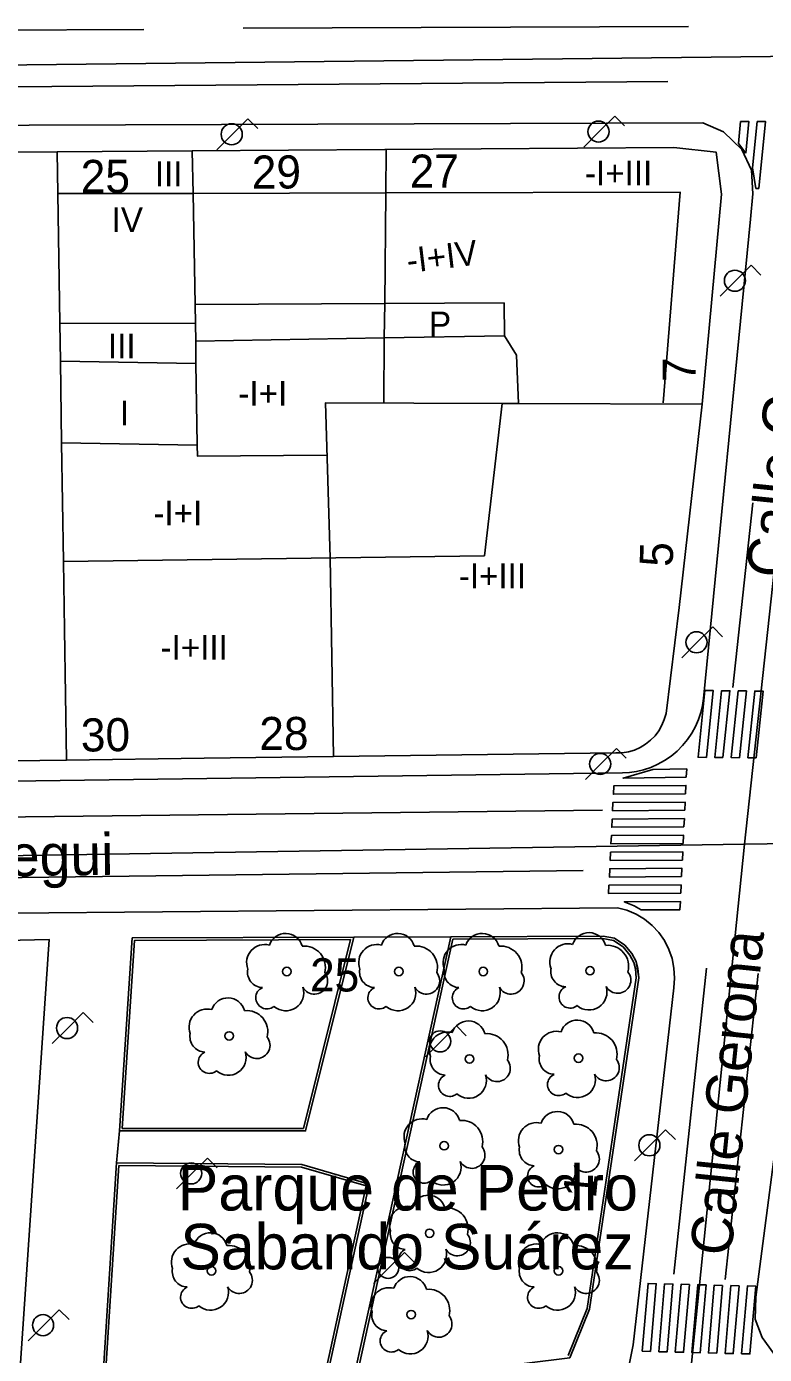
# Model space of a CAD drawing. Extents: x 282771 to 285132, y 4823109 to 4825496.
# Drawn here: x 283003.1 to 283047.7, y 4824352.9 to 4824433.2 of the extents above; entities that cross this region are included whole.
import ezdxf

# ---------------------------------------------------------------- set-up
doc = ezdxf.new("R2010")
doc.units = 0
for name, color, linetype in [('ACERA-BORDILLO', 7, 'Continuous'), ('ACERA-INTERIOR', 7, 'Continuous'), ('ARBOL', 7, 'Continuous'), ('BORDILLO', 7, 'Continuous'), ('CALLE-EJE', 7, 'Continuous'), ('CALLE-TEXTO', 7, 'Continuous'), ('EDIFICIO', 7, 'Continuous'), ('FAROLA', 7, 'Continuous'), ('INTERIOR-EDIFICIO', 7, 'Continuous'), ('MEDIANERA', 7, 'Continuous'), ('NUM-LOCAL', 7, 'Continuous'), ('NUM-PORTAL', 7, 'Continuous'), ('NUM-VADO', 7, 'Continuous'), ('PARQUE-JARDIN-AREA', 7, 'Continuous'), ('PARQUE-JARDIN-TEXTO', 7, 'Continuous'), ('PASO-PEATONES', 7, 'Continuous'), ('SENAL-VIARIA', 7, 'Continuous'), ('TXT-ALTURA-EDIFICIO', 7, 'Continuous'), ('ZONA-VERDE', 7, 'Continuous')]:
    doc.layers.add(name, color=color, linetype=linetype)

msp = doc.modelspace()

# ---------------------------------------------------------------- linework, layer by layer
at = {"layer": 'ACERA-BORDILLO'}
for points in [[(282941.637, 4824386.754), (283039.135, 4824388.075), (283039.556, 4824388.099), (283039.985, 4824388.161), (283040.418, 4824388.262), (283040.85, 4824388.405), (283041.274, 4824388.59), (283041.684, 4824388.816), (283042.074, 4824389.083), (283042.44, 4824389.387), (283042.774, 4824389.724), (283043.074, 4824390.089), (283043.336, 4824390.478), (283043.558, 4824390.884), (283043.738, 4824391.301), (283043.877, 4824391.723), (283043.976, 4824392.146), (283044.037, 4824392.563), (283046.872, 4824421.522), (283047.025, 4824423.063), (283046.94, 4824424.485), (283046.348, 4824425.738), (283045.247, 4824426.805), (283043.995, 4824427.347), (282956.749, 4824427.04)], [(283038.839, 4824379.93), (282983.849, 4824379.43), (282942.342, 4824378.862), (282941.159, 4824378.712), (282940.133, 4824378.39), (282939.066, 4824377.686), (282938.302, 4824376.679), (282938, 4824375.834), (282937.92, 4824374.727), (282938.04, 4824373.801), (282943.253, 4824342.596)], [(283039.561, 4824352.416), (283039.782, 4824353.523), (283042.239, 4824375.09), (283042.289, 4824375.68), (283042.249, 4824376.27), (283042.139, 4824376.85), (283041.949, 4824377.41), (283041.679, 4824377.94), (283041.329, 4824378.43), (283040.929, 4824378.86), (283040.469, 4824379.24), (283039.959, 4824379.54), (283039.409, 4824379.77), (283038.839, 4824379.93)], [(283048.263, 4824353.014), (283047.579, 4824353.961), (283047.157, 4824355.068), (283047.197, 4824356.396), (283049.765, 4824376.004)]]:
    msp.add_lwpolyline(points, dxfattribs=at)
at = {"layer": 'ACERA-INTERIOR'}
msp.add_lwpolyline([(283002.516, 4824348.556), (283004.514, 4824378.006), (283000.089, 4824377.912)], dxfattribs=at)
at = {"layer": 'ARBOL'}
for centre in [(283018.861, 4824376.077), (283025.632, 4824376.077), (283030.733, 4824376.077), (283037.18, 4824376.124), (283015.382, 4824372.182), (283029.898, 4824370.79), (283036.484, 4824370.837), (283028.368, 4824365.55), (283035.278, 4824365.318), (283027.487, 4824360.263), (283014.316, 4824357.99), (283035.278, 4824357.99), (283026.374, 4824355.347)]:
    msp.add_circle(centre, 0.255, dxfattribs=at)
for centre, radius, start, end in [((283018.791, 4824377.337), 1.038, 15.64228, 161.38435), ((283025.562, 4824377.337), 1.038, 15.64228, 161.38435), ((283030.663, 4824377.337), 1.038, 15.64228, 161.38435), ((283037.11, 4824377.384), 1.038, 15.64228, 161.38435), ((283017.531, 4824376.607), 1.097, 75.4318, 200.55608), ((283019.921, 4824376.337), 1.272, 345.03273, 95.79925), ((283024.302, 4824376.607), 1.097, 75.4318, 200.55608), ((283026.692, 4824376.337), 1.272, 345.03273, 95.79925), ((283029.403, 4824376.607), 1.097, 75.4318, 200.55608), ((283031.793, 4824376.337), 1.272, 345.03273, 95.79925), ((283035.85, 4824376.654), 1.097, 75.4318, 200.55608), ((283038.24, 4824376.384), 1.272, 345.03273, 95.79925), ((283035.74, 4824376.084), 0.935, 168.59898, 268.13236), ((283017.421, 4824376.037), 0.935, 168.59898, 268.13236), ((283020.531, 4824375.507), 0.797, 208.96247, 38.99103), ((283024.192, 4824376.037), 0.935, 168.59898, 268.13236), ((283027.302, 4824375.507), 0.797, 208.96247, 38.99103), ((283029.293, 4824376.037), 0.935, 168.59898, 268.13236), ((283032.403, 4824375.507), 0.797, 208.96247, 38.99103), ((283038.85, 4824375.554), 0.797, 208.96247, 38.99103), ((283017.661, 4824374.487), 0.672, 113.73672, 309.4725), ((283018.801, 4824374.787), 1.086, 228.95447, 17.92796), ((283024.432, 4824374.487), 0.672, 113.73672, 309.4725), ((283025.572, 4824374.787), 1.086, 228.95447, 17.92796), ((283029.533, 4824374.487), 0.672, 113.73672, 309.4725), ((283030.673, 4824374.787), 1.086, 228.95447, 17.92796), ((283035.98, 4824374.534), 0.672, 113.73672, 309.4725), ((283037.12, 4824374.834), 1.086, 228.95447, 17.92796), ((283015.312, 4824373.442), 1.038, 15.64228, 161.38435), ((283014.052, 4824372.712), 1.097, 75.4318, 200.55608), ((283016.442, 4824372.442), 1.272, 345.03273, 95.79925), ((283029.828, 4824372.05), 1.038, 15.64228, 161.38435), ((283036.414, 4824372.097), 1.038, 15.64228, 161.38435), ((283013.942, 4824372.142), 0.935, 168.59898, 268.13236), ((283028.569, 4824371.32), 1.097, 75.4318, 200.55608), ((283030.958, 4824371.05), 1.272, 345.03273, 95.79925), ((283035.154, 4824371.367), 1.097, 75.4318, 200.55608), ((283037.544, 4824371.097), 1.272, 345.03273, 95.79925), ((283017.052, 4824371.612), 0.797, 208.96247, 38.99103), ((283014.182, 4824370.592), 0.672, 113.73672, 309.4725), ((283015.322, 4824370.892), 1.086, 228.95447, 17.92796), ((283028.459, 4824370.75), 0.935, 168.59898, 268.13236), ((283031.568, 4824370.22), 0.797, 208.96247, 38.99103), ((283035.044, 4824370.797), 0.935, 168.59898, 268.13236), ((283038.154, 4824370.267), 0.797, 208.96247, 38.99103), ((283028.699, 4824369.2), 0.672, 113.73672, 309.4725), ((283029.838, 4824369.5), 1.086, 228.95447, 17.92796), ((283035.284, 4824369.247), 0.672, 113.73672, 309.4725), ((283036.424, 4824369.547), 1.086, 228.95447, 17.92796), ((283028.298, 4824366.81), 1.038, 15.64228, 161.38435), ((283035.208, 4824366.578), 1.038, 15.64228, 161.38435), ((283027.038, 4824366.08), 1.097, 75.4318, 200.55608), ((283029.428, 4824365.81), 1.272, 345.03273, 95.79925), ((283033.948, 4824365.848), 1.097, 75.4318, 200.55608), ((283036.338, 4824365.578), 1.272, 345.03273, 95.79925), ((283026.928, 4824365.51), 0.935, 168.59898, 268.13236), ((283030.038, 4824364.98), 0.797, 208.96247, 38.99103), ((283033.838, 4824365.278), 0.935, 168.59898, 268.13236), ((283036.948, 4824364.748), 0.797, 208.96247, 38.99103), ((283027.168, 4824363.96), 0.672, 113.73672, 309.4725), ((283028.308, 4824364.26), 1.086, 228.95447, 17.92796), ((283034.078, 4824363.728), 0.672, 113.73672, 309.4725), ((283035.218, 4824364.028), 1.086, 228.95447, 17.92796), ((283026.157, 4824360.793), 1.097, 75.4318, 200.55608), ((283027.417, 4824361.523), 1.038, 15.64228, 161.38435), ((283028.547, 4824360.523), 1.272, 345.03273, 95.79925), ((283014.246, 4824359.25), 1.038, 15.64228, 161.38435), ((283026.047, 4824360.223), 0.935, 168.59898, 268.13236), ((283029.157, 4824359.693), 0.797, 208.96247, 38.99103), ((283035.208, 4824359.25), 1.038, 15.64228, 161.38435), ((283012.986, 4824358.52), 1.097, 75.4318, 200.55608), ((283015.376, 4824358.25), 1.272, 345.03273, 95.79925), ((283033.948, 4824358.52), 1.097, 75.4318, 200.55608), ((283036.338, 4824358.25), 1.272, 345.03273, 95.79925), ((283026.287, 4824358.673), 0.672, 113.73672, 309.4725), ((283027.427, 4824358.973), 1.086, 228.95447, 17.92796), ((283012.876, 4824357.95), 0.935, 168.59898, 268.13236), ((283015.986, 4824357.42), 0.797, 208.96247, 38.99103), ((283033.838, 4824357.95), 0.935, 168.59898, 268.13236), ((283036.948, 4824357.42), 0.797, 208.96247, 38.99103), ((283013.116, 4824356.4), 0.672, 113.73672, 309.4725), ((283014.256, 4824356.7), 1.086, 228.95447, 17.92796), ((283025.044, 4824355.877), 1.097, 75.4318, 200.55608), ((283026.304, 4824356.607), 1.038, 15.64228, 161.38435), ((283034.078, 4824356.4), 0.672, 113.73672, 309.4725), ((283035.218, 4824356.7), 1.086, 228.95447, 17.92796), ((283027.434, 4824355.607), 1.272, 345.03273, 95.79925), ((283024.934, 4824355.307), 0.935, 168.59898, 268.13236), ((283028.044, 4824354.777), 0.797, 208.96247, 38.99103), ((283025.174, 4824353.757), 0.672, 113.73672, 309.4725), ((283026.314, 4824354.057), 1.086, 228.95447, 17.92796)]:
    msp.add_arc(centre, radius, start, end, dxfattribs=at)
at = {"layer": 'BORDILLO'}
for points in [[(283008.749, 4824366.44), (283009.527, 4824378.105), (283022.903, 4824378.156), (283019.994, 4824366.44), (283008.749, 4824366.44)], [(283022.818, 4824351.096), (283028.778, 4824378.178), (283037.968, 4824378.213), (283038.663, 4824378.085), (283039.279, 4824377.671), (283039.702, 4824377.152), (283039.971, 4824376.671), (283040.067, 4824376.258), (283040.129, 4824375.69), (283037.145, 4824355.673), (283035.959, 4824352.74), (283022.818, 4824351.096)], [(283008.579, 4824364.506), (283019.768, 4824364.413), (283023.835, 4824363.231), (283021.146, 4824350.887), (283007.599, 4824349.192), (283008.579, 4824364.506)]]:
    msp.add_lwpolyline(points, dxfattribs=at)
at = {"layer": 'CALLE-EJE'}
for points in [[(283051.679, 4824431.4), (282936.62, 4824430.1), (282927.29, 4824425.68)], [(283051.679, 4824431.4), (283046.519, 4824383.77)], [(283046.519, 4824383.77), (283090.038, 4824384.41), (283123.088, 4824385.39)], [(282933.73, 4824381.99), (283046.519, 4824383.77)], [(283046.519, 4824383.77), (283042.609, 4824345.501)]]:
    msp.add_lwpolyline(points, dxfattribs=at)
at = {"layer": 'EDIFICIO'}
msp.add_lwpolyline([(282996.869, 4824425.55), (283004.989, 4824425.6), (283013.149, 4824425.66), (283042.249, 4824425.85), (283044.809, 4824425.57), (283045.129, 4824423.03), (283043.959, 4824410.344), (283042.559, 4824398.07), (283041.779, 4824391.67), (283041.669, 4824391.3), (283041.529, 4824390.95), (283041.339, 4824390.61), (283041.109, 4824390.31), (283040.839, 4824390.04), (283040.539, 4824389.8), (283040.219, 4824389.61), (283039.869, 4824389.45), (283039.499, 4824389.35), (283039.129, 4824389.29), (283038.749, 4824389.28), (283021.679, 4824389.06), (283013.879, 4824388.96), (283005.549, 4824388.851), (282997.519, 4824388.75)], dxfattribs=at)
at = {"layer": 'FAROLA'}
for p, q in [((283016.512, 4824427.582), (283015.572, 4824426.652)), ((283017.102, 4824426.992), (283016.512, 4824427.582)), ((283038.672, 4824427.745), (283037.732, 4824426.815)), ((283039.262, 4824427.155), (283038.672, 4824427.745)), ((283037.732, 4824426.815), (283036.802, 4824425.875)), ((283015.572, 4824426.652), (283014.642, 4824425.712)), ((283046.913, 4824418.735), (283045.973, 4824417.805)), ((283047.503, 4824418.145), (283046.913, 4824418.735)), ((283045.973, 4824417.805), (283045.043, 4824416.865)), ((283044.595, 4824396.89), (283043.655, 4824395.96)), ((283045.185, 4824396.3), (283044.595, 4824396.89)), ((283043.655, 4824395.96), (283042.725, 4824395.02)), ((283038.776, 4824389.545), (283037.836, 4824388.615)), ((283039.366, 4824388.955), (283038.776, 4824389.545)), ((283037.836, 4824388.615), (283036.906, 4824387.675)), ((283006.566, 4824373.59), (283005.626, 4824372.66)), ((283007.156, 4824373), (283006.566, 4824373.59)), ((283005.626, 4824372.66), (283004.696, 4824371.72)), ((283029.107, 4824372.785), (283028.167, 4824371.855)), ((283029.697, 4824372.195), (283029.107, 4824372.785)), ((283028.167, 4824371.855), (283027.237, 4824370.915)), ((283041.746, 4824366.506), (283040.806, 4824365.576)), ((283042.336, 4824365.916), (283041.746, 4824366.506)), ((283040.806, 4824365.576), (283039.876, 4824364.636)), ((283014.067, 4824364.806), (283013.127, 4824363.876)), ((283014.657, 4824364.216), (283014.067, 4824364.806)), ((283013.127, 4824363.876), (283012.197, 4824362.936)), ((283025.968, 4824359.099), (283025.028, 4824358.169)), ((283026.558, 4824358.509), (283025.968, 4824359.099)), ((283025.028, 4824358.169), (283024.098, 4824357.229)), ((283005.117, 4824355.638), (283004.177, 4824354.708)), ((283005.707, 4824355.048), (283005.117, 4824355.638)), ((283004.177, 4824354.708), (283003.247, 4824353.768))]:
    msp.add_line(p, q, dxfattribs=at)
for centre in [(283015.532, 4824426.652), (283037.692, 4824426.815), (283045.933, 4824417.805), (283043.615, 4824395.96), (283037.796, 4824388.615), (283005.586, 4824372.66), (283028.127, 4824371.855), (283040.766, 4824365.576), (283013.087, 4824363.876), (283024.988, 4824358.169), (283004.137, 4824354.708)]:
    msp.add_circle(centre, 0.637, dxfattribs=at)
at = {"layer": 'INTERIOR-EDIFICIO'}
for points in [[(283032.869, 4824410.386), (283032.729, 4824413.31), (283032.009, 4824414.47), (283031.989, 4824416.46), (283024.793, 4824416.42), (283013.319, 4824416.36), (283013.339, 4824415.23), (283013.359, 4824414.15)], [(283013.359, 4824414.15), (283013.376, 4824412.81)], [(283005.182, 4824412.95), (283005.257, 4824408.018)], [(283013.376, 4824412.81), (283005.182, 4824412.95)], [(283032.869, 4824410.386), (283031.883, 4824410.389), (283030.808, 4824401.18)], [(283005.257, 4824408.018), (283005.366, 4824400.85)], [(283005.366, 4824400.85), (283030.808, 4824401.18)]]:
    msp.add_lwpolyline(points, dxfattribs=at)
at = {"layer": 'MEDIANERA'}
for points in [[(283005.028, 4824423.07), (283004.989, 4824425.6)], [(283013.196, 4824423.08), (283013.149, 4824425.66)], [(283024.84, 4824423.11), (283024.859, 4824425.73)], [(283005.028, 4824423.07), (283013.196, 4824423.08)], [(283005.147, 4824415.25), (283005.028, 4824423.07)], [(283013.196, 4824423.08), (283024.84, 4824423.11)], [(283013.319, 4824416.36), (283013.196, 4824423.08)], [(283024.84, 4824423.11), (283024.793, 4824416.42), (283024.739, 4824414.345), (283024.719, 4824410.44)], [(283041.609, 4824410.43), (283042.629, 4824423.15), (283024.84, 4824423.11)], [(283005.182, 4824412.95), (283005.147, 4824415.25)], [(283005.147, 4824415.25), (283013.339, 4824415.23)], [(283024.739, 4824414.345), (283013.359, 4824414.15)], [(283024.739, 4824414.345), (283032.009, 4824414.47)], [(283005.257, 4824408.018), (283013.44, 4824407.879), (283013.439, 4824407.91), (283013.376, 4824412.81)], [(283021.479, 4824401.059), (283021.203, 4824410.429), (283031.883, 4824410.389)], [(283032.869, 4824410.386), (283043.959, 4824410.344)], [(283021.269, 4824407.26), (283013.457, 4824407.21), (283013.44, 4824407.879)], [(283005.549, 4824388.851), (283005.429, 4824396.743), (283005.366, 4824400.85)], [(283021.679, 4824389.06), (283021.479, 4824401.059)]]:
    msp.add_lwpolyline(points, dxfattribs=at)
at = {"layer": 'PARQUE-JARDIN-AREA'}
msp.add_lwpolyline([(283007.599, 4824349.192), (283008.579, 4824364.506), (283008.749, 4824366.44), (283009.527, 4824378.105), (283022.903, 4824378.156), (283028.778, 4824378.178), (283037.968, 4824378.213), (283038.663, 4824378.085), (283039.279, 4824377.671), (283039.702, 4824377.152), (283039.971, 4824376.671), (283040.129, 4824375.69), (283037.145, 4824355.673), (283035.959, 4824352.74), (283022.818, 4824351.096), (283021.146, 4824350.887)], close=True, dxfattribs=at)
at = {"layer": 'PASO-PEATONES'}
for points in [[(283046.584, 4824425.515), (283046.141, 4824426.098), (283046.275, 4824427.414), (283046.778, 4824427.417)], [(283047.19, 4824423.385), (283046.996, 4824424.629), (283047.281, 4824427.42), (283047.784, 4824427.422), (283047.371, 4824423.386)], [(283044.21, 4824389.01), (283043.708, 4824389.014), (283044.123, 4824393.044), (283044.626, 4824393.04)], [(283045.214, 4824389.001), (283044.712, 4824389.005), (283045.128, 4824393.035), (283045.63, 4824393.031)], [(283046.219, 4824388.992), (283045.717, 4824388.997), (283046.132, 4824393.027), (283046.634, 4824393.022)], [(283047.223, 4824388.984), (283046.721, 4824388.988), (283047.137, 4824393.018), (283047.639, 4824393.014)], [(283042.999, 4824387.811), (283039.174, 4824387.758), (283040.985, 4824388.281), (283043.023, 4824388.311)], [(283042.951, 4824386.811), (283038.592, 4824386.784), (283038.616, 4824387.284), (283042.975, 4824387.311)], [(283042.903, 4824385.811), (283038.543, 4824385.784), (283038.568, 4824386.284), (283042.927, 4824386.311)], [(283042.855, 4824384.81), (283038.495, 4824384.784), (283038.519, 4824385.284), (283042.879, 4824385.31)], [(283042.807, 4824383.81), (283038.447, 4824383.783), (283038.471, 4824384.283), (283042.831, 4824384.31)], [(283042.759, 4824382.81), (283038.399, 4824382.783), (283038.423, 4824383.283), (283042.783, 4824383.31)], [(283042.71, 4824381.809), (283038.351, 4824381.783), (283038.375, 4824382.283), (283042.735, 4824382.31)], [(283042.662, 4824380.809), (283038.303, 4824380.782), (283038.327, 4824381.282), (283042.686, 4824381.309)], [(283039.852, 4824380.035), (283039.247, 4824380.288), (283042.638, 4824380.309), (283042.614, 4824379.809), (283040.261, 4824379.794)], [(283040.33, 4824353.132), (283040.684, 4824357.227), (283041.185, 4824357.215), (283040.831, 4824353.119)], [(283041.331, 4824353.106), (283041.686, 4824357.202), (283042.186, 4824357.19), (283041.832, 4824353.094)], [(283042.333, 4824353.081), (283042.687, 4824357.177), (283043.188, 4824357.164), (283042.834, 4824353.069)], [(283044.19, 4824357.139), (283043.835, 4824353.043), (283043.334, 4824353.056), (283043.689, 4824357.152)], [(283045.191, 4824357.114), (283044.837, 4824353.018), (283044.336, 4824353.031), (283044.69, 4824357.127)], [(283046.193, 4824357.089), (283045.838, 4824352.993), (283045.338, 4824353.006), (283045.692, 4824357.101)], [(283047.194, 4824357.064), (283046.84, 4824352.968), (283046.339, 4824352.98), (283046.694, 4824357.076)]]:
    msp.add_lwpolyline(points, close=True, dxfattribs=at)
at = {"layer": 'SENAL-VIARIA'}
for points in [[(282991.567, 4824432.902), (283010.234, 4824432.979)], [(283016.217, 4824433.068), (283043.133, 4824433.159)], [(282945.019, 4824427.208), (282945.081, 4824429.057), (283041.889, 4824429.84)], [(283047.024, 4824404.393), (283045.816, 4824393.223)], [(283037.935, 4824385.812), (282999.563, 4824385.38)], [(282943.151, 4824381.018), (283036.765, 4824382.174)], [(283042.237, 4824357.794), (283044.221, 4824376.284)], [(283045.349, 4824357.46), (283047.333, 4824375.95)]]:
    msp.add_lwpolyline(points, dxfattribs=at)
at = {"layer": 'ZONA-VERDE'}
for p, q in [((283019.876, 4824366.59), (283022.711, 4824378.005)), ((283028.899, 4824378.029), (283023.01, 4824351.272)), ((283008.91, 4824366.59), (283019.876, 4824366.59)), ((283008.72, 4824364.355), (283007.76, 4824349.363)), ((283021.022, 4824351.023), (283023.658, 4824363.126))]:
    msp.add_line(p, q, dxfattribs=at)
for points in [[(283022.711, 4824378.005), (283009.668, 4824377.955), (283008.91, 4824366.59)], [(283035.853, 4824352.878), (283036.999, 4824355.713), (283039.977, 4824375.693), (283039.919, 4824376.233), (283039.83, 4824376.617), (283039.577, 4824377.067), (283039.177, 4824377.559), (283038.606, 4824377.943), (283037.955, 4824378.063), (283028.899, 4824378.029)], [(283023.658, 4824363.126), (283019.746, 4824364.264), (283008.72, 4824364.355)]]:
    msp.add_lwpolyline(points, dxfattribs=at)

# ---------------------------------------------------------------- texts
at = {"layer": 'CALLE-TEXTO'}
for s, rotation, p in [('Calle Gerona', 84.16634, (283049.1, 4824399.778)), ('Calle Zumalacárregui', 0.9042, (282976.638, 4824381.417)), ('Calle Gerona', 84.16634, (283045.702, 4824358.831))]:
    msp.add_text(s, height=2.5, rotation=rotation, dxfattribs=at).set_placement(p)
at = {"layer": 'NUM-LOCAL'}
for s, rotation, p in [('25', 359.54004, (283020.259, 4824374.884)), ('1', 84.69004, (283037.535, 4824362.329))]:
    msp.add_text(s, height=2, rotation=rotation, dxfattribs=at).set_placement(p)
at = {"layer": 'NUM-PORTAL'}
for s, rotation, p in [('29', 0.37004, (283016.75, 4824423.363)), ('27', 0.37004, (283026.291, 4824423.419)), ('25', 0.37004, (283006.419, 4824423.099)), ('5', 88.63955, (283042.176, 4824400.506)), ('30', 0.50004, (283006.428, 4824389.362))]:
    msp.add_text(s, height=2, rotation=rotation, dxfattribs=at).set_placement(p)
at = {"layer": 'NUM-VADO'}
for s, rotation, p in [('7', 90, (283043.569, 4824411.684)), ('28', 0.00004, (283017.199, 4824389.453))]:
    msp.add_text(s, height=2, rotation=rotation, dxfattribs=at).set_placement(p)
at = {"layer": 'PARQUE-JARDIN-TEXTO'}
for s, p in [('Parque de Pedro ', (283012.273, 4824361.637)), ('Sabando Suárez', (283012.426, 4824358.081))]:
    msp.add_text(s, height=2.75, dxfattribs=at).set_placement(p)
at = {"layer": 'TXT-ALTURA-EDIFICIO'}
for s, rotation, p in [('III', 0.00004, (283010.887, 4824423.51)), ('-I+III', 0.00004, (283036.874, 4824423.56)), ('IV', 0.00004, (283008.28, 4824420.74)), ('-I+IV', 6.93004, (283026.191, 4824418.269)), ('P', 0.00004, (283027.453, 4824414.44)), ('III', 0.00004, (283008.057, 4824413.11)), ('-I+I', 0.00004, (283015.935, 4824410.25)), ('I', 0.00004, (283008.778, 4824409.06)), ('-I+I', 0.00004, (283010.801, 4824403.027)), ('-I+III', 0.00004, (283029.25, 4824399.226)), ('-I+III', 0.00004, (283011.23, 4824394.905))]:
    msp.add_text(s, height=1.5, rotation=rotation, dxfattribs=at).set_placement(p)

doc.saveas('drawing.dxf')
